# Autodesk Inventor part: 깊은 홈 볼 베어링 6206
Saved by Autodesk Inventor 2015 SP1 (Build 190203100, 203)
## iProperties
Created: 2026-07
Part Number: 깊은 홈 볼 베어링 6206
Material: 일반
Document SubType Name: Modeling
Designer: user
Density: 1 g/cm^3
Appearance: 기본값
Author: user
Author: jhkim
Description: 깊은 그루브 볼 베어링
Creation Date: 2026-07-01
Sending System: Autodesk Inventor 2027
Preprocessor: ST-DEVELOPER v20.1
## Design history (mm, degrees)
node "깊은 홈 볼 베어링 62061"
body "Solid1"
node "Solid1_1"
node "Solid1_2"
node "Solid1_3"
node "Solid1_4"
node "Solid1_5"
node "Solid1_6"
node "Solid1_7"
node "Solid1_8"
node "Solid1_9"
node "Solid1_10"
node "기준1"
node "기준2"
node "기준3"
node "기준4"
node "기준5"
node "기준6"
node "기준7"
node "기준8"
node "기준9"
node "기준10"
node "기준11"
